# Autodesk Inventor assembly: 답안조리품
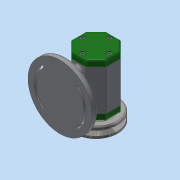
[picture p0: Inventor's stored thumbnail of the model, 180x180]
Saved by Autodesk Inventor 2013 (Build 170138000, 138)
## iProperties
Created: 2017-06
Part Number: 답안조리품
Document SubType Name: Assembly
Designer: dgall
Author: dgall
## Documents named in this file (14)
- C:\Users\dgall\Desktop\470607V1010\답안조리품.iam
- C:\Users\dgall\Desktop\470607V1010\본체.ipt
- C:\Users\dgall\Desktop\470607V1010\베어링 15 x 32 x 9.ipt
- C:\Users\dgall\Desktop\470607V1010\뒤커버.ipt
- C:\Users\dgall\Desktop\470607V1010\앞커버.ipt
- C:\Users\dgall\Desktop\470607V1010\볼트 M4 x 12.ipt
- C:\Users\dgall\Desktop\470607V1010\오일 실 15 25 7.ipt
- C:\Users\dgall\Desktop\470607V1010\V벨트풀리.ipt
- C:\Users\dgall\Desktop\470607V1010\축.ipt
- C:\Users\dgall\Desktop\470607V1010\키 3 x 3 x 12.ipt
- C:\Users\dgall\Desktop\470607V1010\스프링와셔 8.ipt
- C:\Users\dgall\Desktop\470607V1010\와셔 8x17.ipt
- C:\Users\dgall\Desktop\470607V1010\고무캡.ipt
- C:\Users\dgall\Desktop\470607V1010\너트 M 8.ipt
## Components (2 placed, 2 different names)
1. V벨트풀리:1
2. 고무캡:1
